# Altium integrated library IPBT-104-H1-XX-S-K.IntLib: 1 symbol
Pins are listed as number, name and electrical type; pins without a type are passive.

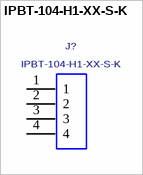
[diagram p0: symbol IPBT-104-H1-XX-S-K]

## IPBT-104-H1-XX-S-K
designator J?
.165 SINGLE ROW TERMINAL ASSEMBLY.; MANUFACTURER: SAMTEC
footprint IPBT-104-H1-XX-S-K
pins: 1, 2, 3, 4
